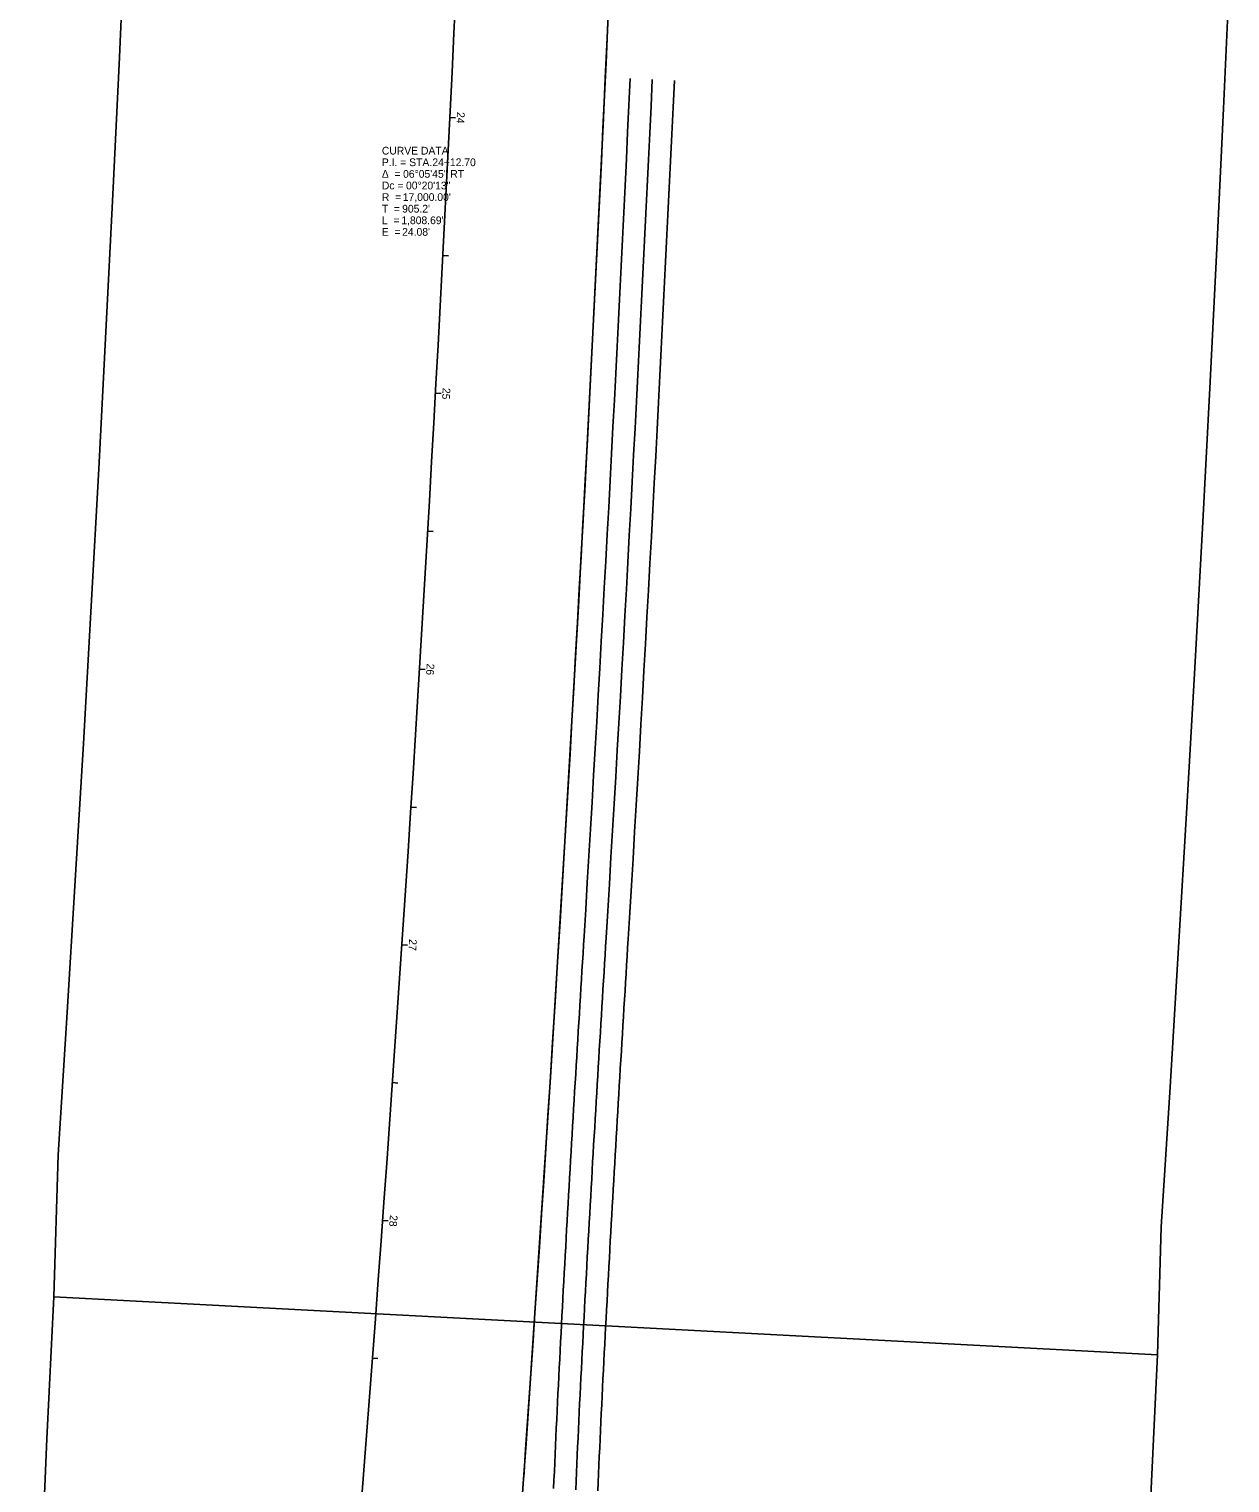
# Model space of a CAD drawing. Extents: x 172043 to 172847, y 249504 to 259737.
# Drawn here: x 172346 to 172781, y 256843 to 257369 of the extents above; entities that cross this region are included whole.
import ezdxf

# ---------------------------------------------------------------- set-up
doc = ezdxf.new("R2010")
doc.units = 0
for name, color, linetype in [('PM_X_Surveyed_Line', 7, 'Continuous'), ('PV_X_EOP', 7, 'Continuous'), ('PV_X_Shoulder', 7, 'Continuous'), ('RW_X_CL_100_Distances', 7, 'Continuous')]:
    doc.layers.add(name, color=color, linetype=linetype)

msp = doc.modelspace()

# ---------------------------------------------------------------- linework, layer by layer
at = {"layer": 'PM_X_Surveyed_Line'}
for p, q in [((172498.25, 257336.78), (172500.25, 257336.68)), ((172498.25, 257336.78), (172500.25, 257336.68)), ((172495.73, 257286.85), (172497.72, 257286.74)), ((172493.05, 257236.92), (172495.05, 257236.81)), ((172493.05, 257236.92), (172495.05, 257236.81)), ((172490.23, 257187), (172492.23, 257186.88)), ((172487.26, 257137.09), (172489.26, 257136.96)), ((172487.26, 257137.09), (172489.26, 257136.96)), ((172484.15, 257087.18), (172486.15, 257087.06)), ((172480.89, 257037.29), (172482.89, 257037.16)), ((172480.89, 257037.29), (172482.89, 257037.16)), ((172477.48, 256987.41), (172479.48, 256987.27)), ((172473.93, 256937.53), (172475.92, 256937.39)), ((172473.93, 256937.53), (172475.92, 256937.39)), ((172470.23, 256887.67), (172472.22, 256887.52))]:
    msp.add_line(p, q, dxfattribs=at)
msp.add_arc((155518.73, 258170.95), 17000, 354.099581, 0.195474, dxfattribs=at)
msp.add_arc((155518.73, 258170.95), 17000, 354.099581, 0.195474, dxfattribs=at)
at = {"layer": 'PV_X_EOP'}
for radius, start, end in [(21551.92, 355.091243, 0.046603), (21576.92, 356.510763, 357.33743)]:
    msp.add_arc((151025.86, 258352.49), radius, start, end, dxfattribs=at)
msp.add_open_spline([(172551.77, 256839.6), (172552.5, 256856.26), (172554.08, 256889.55), (172556.81, 256939.48), (172559.73, 256989.39), (172561.77, 257022.66), (172562.78, 257039.3)], degree=3, dxfattribs=at)
at = {"layer": 'PV_X_Shoulder'}
for points in [[(172354.92, 256909.87), (172754.37, 256888.9), (172755.61, 256935.22), (172758.85, 256985.79), (172761.97, 257036.37), (172764.98, 257086.95), (172767.86, 257137.54), (172770.63, 257188.14), (172773.28, 257238.75), (172775.81, 257289.36), (172778.23, 257339.98), (172780.53, 257390.6), (172380.92, 257408.27), (172378.66, 257358.58), (172376.29, 257308.89), (172373.8, 257259.21), (172371.2, 257209.53), (172368.49, 257159.86), (172365.65, 257110.2), (172362.7, 257060.54), (172359.64, 257010.89), (172356.46, 256961.25)], [(172345.99, 256399.91), (172745.99, 256399.15), (172746.09, 256449.15), (172746.18, 256499.15), (172746.28, 256549.15), (172746.37, 256599.15), (172746.66, 256647.48), (172747.36, 256695.73), (172748.49, 256743.97), (172750.04, 256792.2), (172752.01, 256840.45), (172754.37, 256888.9), (172354.92, 256909.87), (172352.41, 256858.44), (172350.3, 256806.77), (172348.64, 256755.05), (172347.43, 256703.32), (172346.68, 256651.58), (172346.37, 256599.91), (172346.28, 256549.91), (172346.18, 256499.91), (172346.09, 256449.91)]]:
    msp.add_lwpolyline(points, close=True, dxfattribs=at)
at = {"layer": 'RW_X_CL_100_Distances'}
for radius, start, end in [(21551.92, 355.987979, 0.046603), (21560.92, 356.511134, 357.33743), (21568.92, 356.510949, 357.33743), (21576.92, 356.510763, 357.33743)]:
    msp.add_arc((151025.86, 258352.49), radius, start, end, dxfattribs=at)
for points in [[(172535.79, 256840.44), (172536.52, 256857.11), (172538.1, 256890.46), (172540.84, 256940.45), (172543.76, 256990.44), (172545.81, 257023.75), (172546.82, 257040.41)], [(172543.78, 256840.02), (172544.51, 256856.68), (172546.09, 256890), (172548.83, 256939.96), (172551.74, 256989.91), (172553.79, 257023.21), (172554.8, 257039.85)], [(172551.77, 256839.6), (172552.5, 256856.26), (172554.08, 256889.55), (172556.81, 256939.48), (172559.73, 256989.39), (172561.77, 257022.66), (172562.78, 257039.3)]]:
    msp.add_open_spline(points, degree=3, dxfattribs=at)

# ---------------------------------------------------------------- texts
at = {"layer": 'PM_X_Surveyed_Line'}
for s, rotation, p in [('24', 267.1874, (172500.86, 257338.81)), ('25', 266.8504, (172495.67, 257238.96)), ('26', 266.5134, (172489.9, 257139.17)), ('27', 266.1763, (172483.54, 257039.42)), ('28', 265.8393, (172476.58, 256939.56))]:
    msp.add_text(s, height=2.8, rotation=rotation, dxfattribs=at).set_placement(p)
for s, p in [('CURVE DATA', (172473.65, 257323.35)), ('P.I. = STA. ', (172473.65, 257319.15)), ('24+12.70', (172491.92, 257319.15)), ('Δ  = ', (172473.65, 257314.95)), ('06°05\'45" RT', (172481.33, 257314.95)), ('Dc = ', (172473.65, 257310.75)), ('00°20\'13"', (172482.39, 257310.75)), ('R  = ', (172473.65, 257306.55)), ("17,000.00'", (172481.23, 257306.55)), ('T  = ', (172473.65, 257302.35)), ('L  = ', (172473.65, 257298.15)), ("1,808.69'", (172480.69, 257298.15)), ("905.2'", (172480.99, 257302.35)), ('E  = ', (172473.65, 257293.95)), ("24.08'", (172480.99, 257293.95))]:
    msp.add_text(s, height=2.8, dxfattribs=at).set_placement(p)

doc.saveas('drawing.dxf')
